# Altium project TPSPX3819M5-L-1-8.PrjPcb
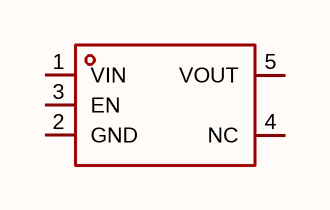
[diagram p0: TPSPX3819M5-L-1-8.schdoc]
1 sheet, 1 parts. Net scope: global (net labels, ports and power ports of the same name join across sheets).

## Sheet TPSPX3819M5-L-1-8.schdoc
size 127 x 101 mm

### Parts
U?  tpspx3819m5-l-1-8  [SOT-23-5_L3.0-W1.5-P0.95-LS2.8-BL]  (value not drawn)

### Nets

Not connected (* = marked no-connect by the designer): U? 1(VIN) 2(GND) 3(EN) 4(NC) 5(VOUT)

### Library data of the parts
U? = tpspx3819m5-l-1-8: 输出极性:正极;工作电压:20V;输出电压:1.8V;输出电流:500mA;电源纹波抑制比(PSRR):70dB@(1kHz);输出类型:固定;; Manufacturer: TECH PUBLIC(台舟); AddInBom: yes; ModelId: 424d41c645fb4cc2a3598f66fad27964; ModelTransform: 118.11,110.236,0,0,0,0,0,0,0; Output Configuration: 正极; Voltage - Supply: 20V; Output Voltage: 1.8V; Output Current: 500mA; Voltage Dropout: 500mV@(100mA); standby current: 2.5uA; Output Type: 固定; Number of Outputs: 1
